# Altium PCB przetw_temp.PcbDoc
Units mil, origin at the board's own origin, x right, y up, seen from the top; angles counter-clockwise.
Board outline 2325 x 1695 mil, 2 copper layers (Top Layer, Bottom Layer); 41 components, 22 nets, 104 pads, 2 vias.
Unrouted connection lines stored in the file: 1.
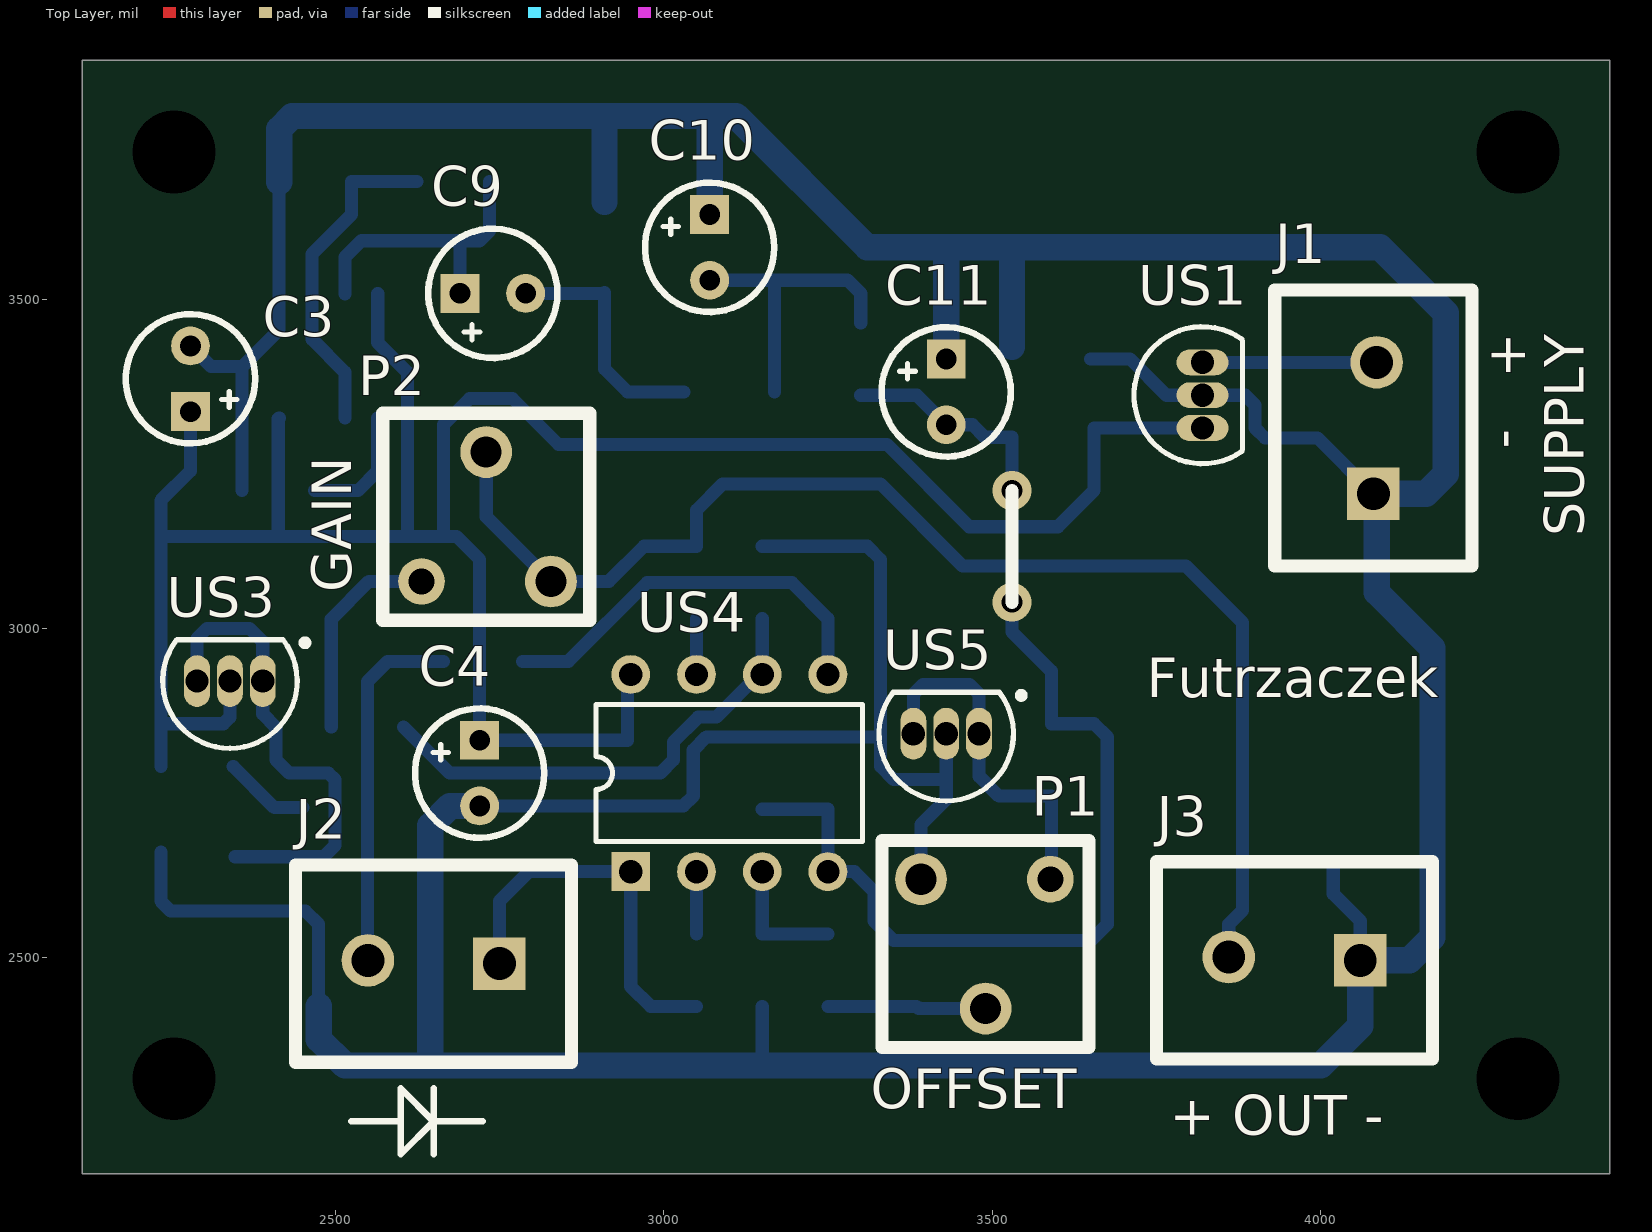
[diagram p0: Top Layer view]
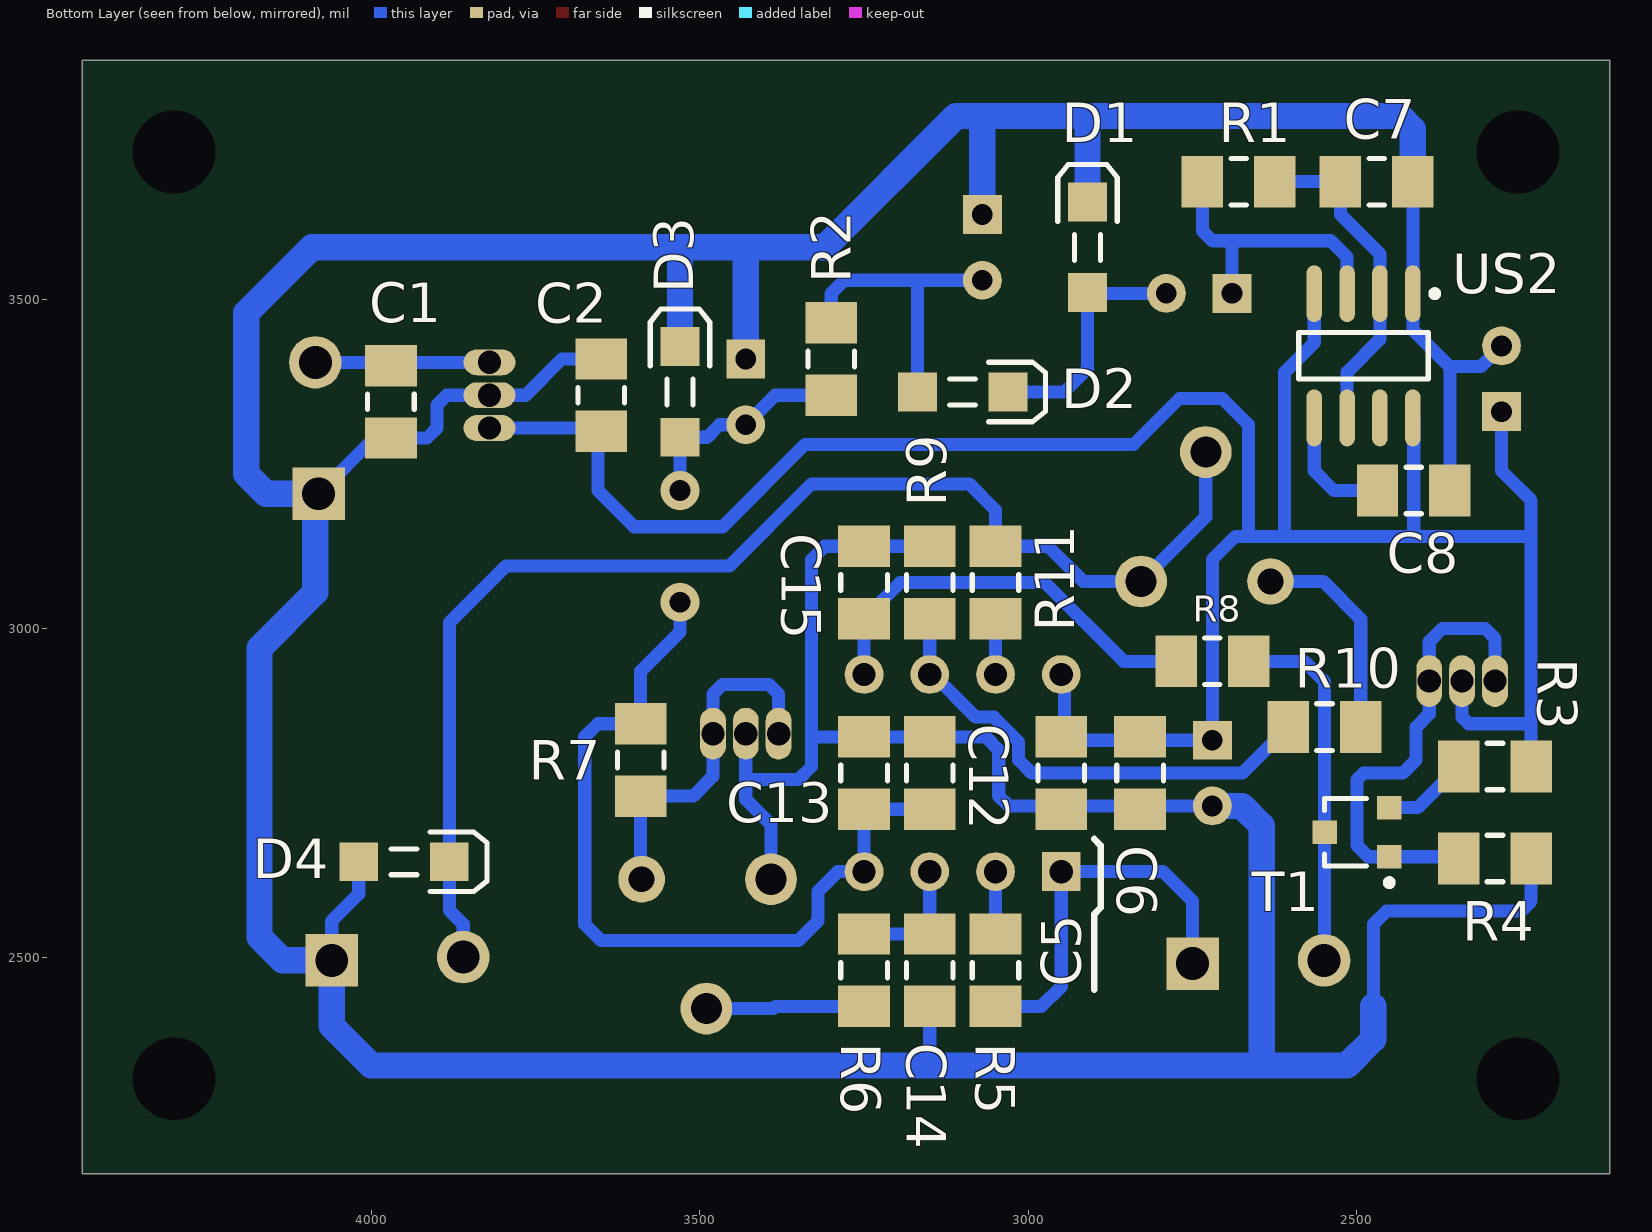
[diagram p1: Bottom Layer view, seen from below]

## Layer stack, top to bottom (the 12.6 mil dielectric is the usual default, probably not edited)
Top Layer: signal copper 1.4
Dielectric: dielectric 12.6, FR-4, Dk 4.8
Bottom Layer: signal copper 1.4

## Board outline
2115,2170 4440,2170 4440,3865 2115,3865

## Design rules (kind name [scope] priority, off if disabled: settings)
Clearance [All] p1: gap=10
PolygonConnect [All] p1: connectstyle=Relief reliefconductorwidth=10 reliefentries=4 polygonreliefangle="90 Angle"
RoutingVias [All] p1: holewidth=28 width=50 viastyle="Through Hole" minholewidth=28 minwidth=50 maxholewidth=28 maxwidth=50
SilkscreenOverComponentPads [All] p1: minsilkscreentomaskgap=10
SolderMaskExpansion [All] p1: expansion=4
Width [All] p1: maxlimit=100 minlimit=10 preferedwidth=20
27 further rules are at their usual default settings.

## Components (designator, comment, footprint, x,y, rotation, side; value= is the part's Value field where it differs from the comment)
C1 "100n" MELF-1206 3970,3345 r90 bottom
C2 "100n" MELF-1206 3650,3355 r270 bottom
C3 "100u/25V" "2,5/5mm elektrolit" 2280,3380 r90 top
C4 "100u/25V" "2,5/5mm elektrolit" 2720,2780 r270 top
C5 "100n" MELF-1206 2950,2780 r90 bottom
C6 "4,7n" MELF-1206 2830,2780 r90 bottom
C7 "4,7n" MELF-1206 2470,3680 r0 bottom
C8 "100n" MELF-1206 2413.62,3210 r0 bottom
C9 "100u/25V" "2,5/5mm elektrolit" 2740,3510 r0 top
C10 "100u/25V" "2,5/5mm elektrolit" 3070,3580 r270 top
C11 "100u/25V" "2,5/5mm elektrolit" 3430,3360 r270 top
C12 "100n" MELF-1206 3150,2780 r270 bottom
C13 "4,7n" MELF-1206 3250,2780 r270 bottom
C14 "100n" MELF-1206 3150,2480 r90 bottom
C15 "100n" MELF-1206 3250,3070 r270 bottom
D1 "1N4148" "dioda MINIMELF" 2910,3580 r90 bottom
D2 "1N4148" "dioda MINIMELF" 3100,3360 r180 bottom
D3 "5,1V" "dioda MINIMELF" 3530,3360 r90 bottom
D4 "5,1V" "dioda MINIMELF" 3950,2645 r180 bottom
J1 "ARK2" "ARK2 5mm" 4080,3305 r90 top
J2 "ARK2" "ARK2 5mm" 2650,2490 r180 top
J3 "ARK2" "ARK2 5mm" 3960,2495 r180 top
P1 "100k" "pot mont poziom" 3490,2520 r180 top
P2 "100k" "pot mont poziom" 2730,3170 r0 top
R1 "3,9k" MELF-1206 2680,3680 r0 bottom
R2 "47" MELF-1206 3300,3410 r270 bottom
R3 "1k 1%" MELF-1206 2290,2790 r180 bottom
R4 "2,2k" MELF-1206 2290,2650 r0 bottom
R5 "100k" MELF-1206 3050,2480 r270 bottom
R6 "100k" MELF-1206 3250,2480 r90 bottom
R7 "3,9k" MELF-1206 3590,2800 r90 bottom
R8 "100k" MELF-1206 2720,2950 r0 bottom
R9 "100k" MELF-1206 3150,3070 r270 bottom
R10 "0" MELF-1206 2549.21,2850 r0 bottom
R11 "470" MELF-1206 3050,3070 r270 bottom
T1 "BC857" 318-08 2500,2690 r90 bottom
US1 "78L09" TO92 3820,3355 r0 top
US2 "NE555" 751-02_N 2490,3415 r270 bottom
US3 "LM385Z-2.5" Z03A 2340,2920 r90 top
US4 "TLC272" JG008 3100,2780 r0 top
US5 "LM385Z-1.2" Z03A 3430,2840 r90 top

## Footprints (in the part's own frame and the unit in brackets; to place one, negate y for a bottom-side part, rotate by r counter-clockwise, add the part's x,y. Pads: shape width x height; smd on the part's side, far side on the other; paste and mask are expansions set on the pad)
"2,5/5mm elektrolit" [mm]
  rect 1.5x1.5 hole 0.8: 1(-1.27,0)
  round 1.5 hole 0.8: 2(1.27,0)
  silkscreen extent -2.5,-2.5 2.5,2.5, body extent -2.51,-2.51 2.51,2.51
318-08 [mm] "SOT-23; 3 Leads; Body 3.0 x 2.6 mm, inc. leads (LxW max)"
  rect 0.9x0.95 smd: 1(-0.95,-1.25) 2(0.95,-1.25) 3(0,1.25)
  silkscreen extent -2.07,-1.37 1.3,1.25
751-02_N [mm] "SOIC, 8-Leads, Body 4.9x3.9mm, Pitch 1.27mm, IPC Medium Density"
  oval 2.2x0.6 smd: 1(-2.4,1.905) 2(-2.4,0.635) 3(-2.4,-0.635) 4(-2.4,-1.905) 5(2.4,-1.905) 6(2.4,-0.635) 7(2.4,0.635) 8(2.4,1.905)
  silkscreen extent -2.52,-2.5 0.9,2.88, body extent -1.95,-2.45 1.95,2.45, height 1.75
"ARK2 5mm" [mil]
  rect 80x80 hole 50: 1(-100,0)
  round 80 hole 50: 2(100,-5)
  silkscreen extent -210,-150 210,150, body extent -220,-160 220,160, height 394
"dioda MINIMELF" [mm] "SMT LED; 2 Flat Leads"
  rect 1.5x1.5 smd: 1(-1.75,0) 2(1.75,0)
  silkscreen extent -0.5,-1.15 3.2,1.15
JG008 [mm] "DIP; 8 Leads; Row Spacing 7.62 mm; Pitch 2.54 mm"
  rect 1.5x1.5 hole 0.9: 1(-3.81,-3.81)
  round 1.5 hole 0.9: 2(-1.27,-3.81) 3(1.27,-3.81) 4(3.81,-3.81) 5(3.81,3.81) 6(1.27,3.81) 7(-1.27,3.81) 8(-3.81,3.81)
  silkscreen extent -5.15,-2.65 5.15,2.65
MELF-1206 [mm] "Metal Electrode Face (MELF) Resistor; Body 3.2 x 1.8 mm (LxDia)"
  rect 1.6x2 smd: 1(-1.4,0) 2(1.4,0)
  silkscreen extent -0.3,-0.9 0.3,0.9, body extent -2.3,-1.1 2.3,1.1, height 1.85
"pot mont poziom" [mm]
  round 1.8 hole 1: a(-2.5,-2.5)
  round 2 hole 1.2: b(2.5,-2.5) c(0,2.5)
  silkscreen extent -4,-4 4,4
TO92 [mm] "TO, Flat Index; 3 In-Line, Axial Leads; Body Dia. 4.8mm; Leads 0.51 x 0.51 mm (max)"
  oval 2x1 hole 0.9: 1(0,-1.27) 2(0,0) 3(0,1.27)
  silkscreen extent -2.65,-2.65 1.55,2.65
Z03A [mm] "TO, Flat Index; 3 In-Line, Axial Leads; Body Dia. 5mm; Leads 0.55 x 0.50 mm (max)"
  oval 2x1 hole 0.9: 1(0,-1.27) 2(0,0) 3(0,1.27)
  silkscreen extent -2.6,-3.03 1.6,2.6, body extent -2.61,-2.61 1.6,2.61, height 5.2

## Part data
C1 C2 C5 C6 C7 C8 C12 C13 C14 C15: library part kondensator
C3 C4 C9 C10 C11: library part "kond biegunowy", "Polarized Capacitor"
D1 D2: library part Diode, "Default Diode"
D3 D4: library part "D Zener", "Zener Diode"
P1 P2: library part "pot mont"
R1 R2 R3 R4 R5 R6 R7 R8 R9 R10 R11: library part rezystor
T1: library part BC857ALT1, "General Purpose Transistor PNP Silicon"
US1: library part L78L08CZ, "Positive Voltage Regulator"
US2: library part MC1455D, "Timing Circuit"
US3 US5: library part LM285Z, "Adjustable Micropower Voltage Reference"
US4: library part TLC272AIJG, "LinCMOS Precision Dual Operational Amplifier"

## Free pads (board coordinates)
  round 0 hole 125.98: 0(2255,2315) 1(4300,2315) 2(4300,3725) 3(2255,3725)

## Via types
v1: diameter 59.06, hole 31.5, Top Layer to Bottom Layer, 2 vias

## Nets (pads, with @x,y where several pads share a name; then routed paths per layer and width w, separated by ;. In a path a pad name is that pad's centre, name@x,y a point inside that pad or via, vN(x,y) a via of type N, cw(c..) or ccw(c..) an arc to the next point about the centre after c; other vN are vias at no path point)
9V: C2.2 C3.1 C4.1 C5.2 C6.2 R3.2 US1.1 US2.4 US2.8 US3.2 US4.8 | length 3925.3
  Bottom Layer w20: R3.2 2234.88,2855 ; C3.1 2280,3240 2234.88,3194.88 2234.88,3140 ; US3.2 2340,2865 2330,2855 2234.88,2855 ; 2413.62,3141.38 2413.62,3319.13 US2.8 ; US2.4 2565,3435 2610,3390 2610,3140 ; US4.8@2944.88,2924.88 2944.88,2830 C4.1 2720,3105 2685,3140 2665,3140 ; US1.1 3655.12,3305 3655.12,3210.12 3599.88,3154.88 3465.12,3154.88 3340,3280 2840,3280 2770,3350 2705,3350 2665,3310 2665,3140 ; 2234.88,2855 2234.88,3140 ; 2234.88,3140 2610,3140 ; 2610,3140 2665,3140
-5,1V: C11.2 C12.2 C13.2 D3.1 R2.2 R7.2 US4.4 | length 1625.7
  Bottom Layer w20: C12.2 C13.2 US4.4 3290,2630 3320,2600 3320,2555 3350,2525 3650,2525 3675,2550 3675,2835 3654.88,2855.12 R7.2 3590,2935 3530,2995 v1(3530,3040) ; R2.2 3385.12,3354.88 C11.2 3470,3310 3488.9,3291.1 D3.1 v1(3530,3210)
GND: C1.1 C2.1 C3.2 C4.2 C5.1 C6.1 C7.1 C8.1 C10.1 C11.1 C12.1 C13.1 C14.1 C15.1 D1.2 D3.2 D4.1 J1.1 J3.1 P1.b R4.1 R9.1 US1.2 US2.1 US5.2 | length 9386.3
  Bottom Layer w20: R4.1@2234.88,2660 2234.88,2585.12 2250,2570 2455,2570 2475,2550 2475,2425 ; C3.2 2311.5,3398.5 2358.5,3398.5 ; C8.1 2358.5,3398.5 ; C7.1 2414.88,3454.88 2358.5,3398.5 ; C4.2 3030,2730 3045,2745 3045,2815 3065.12,2835.12 C12.1 C13.1 3330,2835.12 ; 3150,2335 C14.1 ; R9.1 C15.1 3309.88,3125.12 3330,3105 3330,2835.12 ; P1.b 3391.57,2701.57 3430,2740 3430,2770 ; US5.2 3430,2770 ; C2.1 3709.88,3410.12 3765,3355 US1.2 3885,3355 3900,3340 3900,3305 3915.12,3289.88 C1.1 3995.12,3289.88 J1.1 ; D4.1 4018.9,2596.1 4060,2555 J3.1 ; 3330,2835.12 3330,2790 3350,2770 3430,2770
  Bottom Layer w40: C7.1 2414.88,3759.88 2435,3780 2910,3780 ; 2475,2425 2475,2375 2515,2335 2645,2335 ; C4.2 2675,2730 2645,2700 2645,2335 ; D1.2 2910,3780 ; C10.1 3070,3775 ; C11.1 3430,3580 ; D3.2 3530,3580 ; J1.1 4160,3205 4190,3235 4190,3480 4090,3580 3530,3580 ; J1.1@4085,3200 4085,3055 4170,2970 4170,2530 4135,2495 J3.1 4060,2395 4000,2335 3150,2335 2645,2335 ; 2910,3780 3110,3780 3310,3580 3430,3580 ; 3430,3580 3530,3580
NetC1_2: C1.2 J1.2 US1.3 | length 265
  Bottom Layer w20: US1.3 J1.2
NetC7_2: C7.2 R1.1 US2.2 US2.6 | length 504.9
  Bottom Layer w20: US2.6 2515,3390 2465,3440 US2.2 2465,3570 2525.12,3630.12 C7.2 R1.1
NetC8_2: C8.2 US2.5 | length 189.2
  Bottom Layer w20: C8.2 2535,3210 2565,3240 US2.5
NetC9_1: C9.1 R1.2 US2.3 | length 442.1
  Bottom Layer w20: US2.3 2515,3565 2540,3590 2720,3590 2735.12,3605.12 R1.2 ; C9.1 2690,3585
NetC9_2: C9.2 D1.1 D2.2 | length 370.6
  Bottom Layer w20: C9.2 D1.1@2908.9,3510 ; D1.1 2910,3395 2945,3360 D2.2
NetC10_2: C10.2 D2.1 R2.1 | length 452.1
  Bottom Layer w20: C10.2 3280,3530 3300,3510 R2.1 ; D2.1 3168.9,3528.9
NetC14_2: C14.2 R6.2 US4.3 | length 194.9
  Bottom Layer w20: US4.3 C14.2 R6.2
NetC15_2: C15.2 R8.2 US4.5 | length 622.3
  Bottom Layer w20: R8.2@2785.12,2950 2855,2950 2975,3070 3194.88,3070 C15.2 US4.5
NetD4_2: D4.2 J3.2 P2.b P2.c R11.1 | length 1989
  Bottom Layer w20: P2.c 2730,3170 P2.b 2916.57,3071.57 2970.12,3125.12 R11.1 3050,3180 3090,3220 3330,3220 3455,3095 3795,3095 3881.1,3008.9 D4.2 3881.1,2571.1 3860,2550 J3.2
NetJ2_1: J2.1 R5.2 US4.1 | length 601.1
  Bottom Layer w20: J2.1 2750,2585 2795,2630 US4.1 2950,2455 2980.12,2424.88 R5.2
NetJ2_2: J2.2 R8.1 T1.3 | length 551.8
  Bottom Layer w20: J2.2@2549.21,2495.79 T1.3 2549.21,2919.21 2580,2950 R8.1
NetP1_a: P1.a R7.1 US5.1 US5.3 | length 544.8
  Bottom Layer w20: US5.3 3380,2900 3395,2915 3465,2915 3480,2900 US5.1 3480,2775 3510.12,2744.88 R7.1 P1.a@3590,2620
NetP1_c: P1.c R6.1 | length 241.5
  Bottom Layer w20: R6.1 3384.88,2424.88 ; 3385,2425 3384.88,2424.88 ; P1.c 3388.19,2421.57 3384.88,2424.88
NetP2_a: P2.a R10.1 | length 325.4
  Bottom Layer w20: R10.1 2494.09,3014.09 2551.57,3071.57 P2.a
NetR3_1: R3.1 T1.2 | length 131.6
  Bottom Layer w20: R3.1 2407.72,2727.4 T1.2
NetR4_2: R4.2 T1.1 US3.1 US3.3 | length 729.7
  Bottom Layer w20: US3.3 2290,2985 2305,3000 2370,3000 2390,2980 US3.1 2390,2870 2410,2850 2410,2800 2430,2780 2490,2780 2500,2770 2500,2670 2482.6,2652.6 T1.1 R4.2@2347.72,2652.6
NetR5_1: R5.1 US4.2 | length 94.9
  Bottom Layer w20: R5.1 US4.2
NetR9_2: R9.2 R10.2 US4.6 | length 737.7
  Bottom Layer w20: R10.2 2674.33,2780 2995,2780 3015,2800 3015,2827.43 3052.69,2865.12 3080.12,2865.12 3145,2930 US4.6 R9.2
NetR11_2: R11.2 US4.7 | length 84.9
  Bottom Layer w20: US4.7 R11.2
pads on no net: US2.7

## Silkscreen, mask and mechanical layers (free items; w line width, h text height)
Top Overlay:
  lines w10: 2525,2250 2600,2250 ; 2650,2200 2650,2300 ; 2725,2250 2650,2250 ; 2650,2250 2600,2300 2600,2200 2650,2250
  lines w20: 3530,3040 3530,3210
  text "+   -" at 4260,3450 h60 r270
  text "SUPPLY" at 4400,3140 h60 r90
  text "GAIN" at 2525,3055 h60 r90
  text "Futrzaczek" at 3735,2895 h60
  text "OFFSET" at 3315,2270 h60
  text "+ OUT -" at 3770,2230 h60
Bottom Overlay:
  lines w10: 2900,2450 2900,2565 2890,2575 2890,2670 2900,2680
Mechanical 1:
  the board outline again, w10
